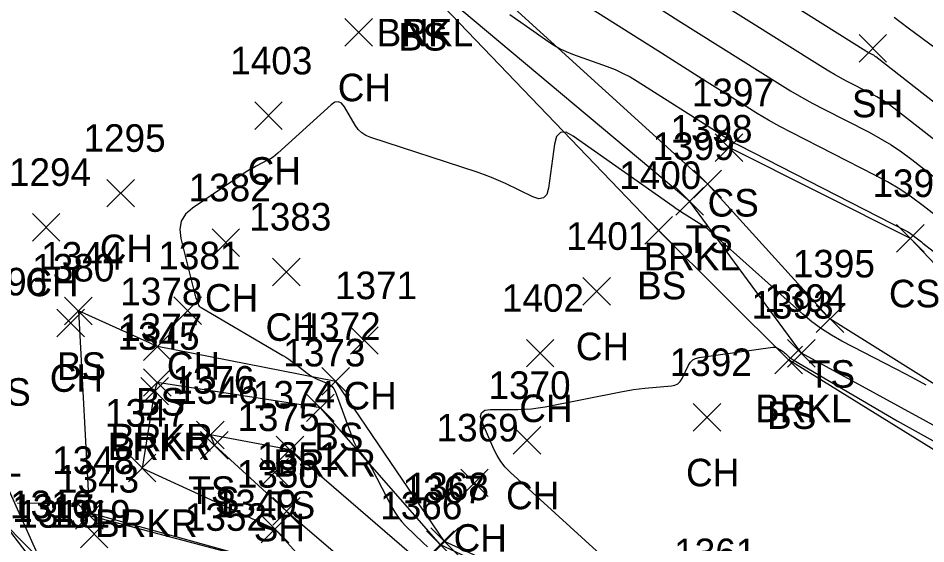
# Model space of a CAD drawing. Extents: x 1592612 to 1596497, y 111838 to 113741.
# Drawn here: x 1592923.4 to 1592989.2, y 113267.9 to 113306.1 of the extents above; entities that cross this region are included whole.
import ezdxf

# ---------------------------------------------------------------- set-up
doc = ezdxf.new("R2010")
doc.units = 0
for name, color, linetype in [('L_A', 7, 'Continuous'), ('L_I', 7, 'Continuous'), ('L_TIC', 7, 'Continuous'), ('LAWE', 7, 'Continuous'), ('LELB', 7, 'Continuous'), ('LSOGCMA', 7, 'Continuous'), ('LSOGCMI', 7, 'Continuous')]:
    doc.layers.add(name, color=color, linetype=linetype)

msp = doc.modelspace()

# ---------------------------------------------------------------- linework, layer by layer
at = {"layer": 'L_TIC'}
for points in [[(1592947.083, 113304.028), (1592949.083, 113306.028)], [(1592949.083, 113304.028), (1592947.083, 113306.028)], [(1592984.338, 113302.867), (1592986.338, 113304.867)], [(1592986.338, 113302.867), (1592984.338, 113304.867)], [(1592940.548, 113297.976), (1592942.548, 113299.976)], [(1592942.548, 113297.976), (1592940.548, 113299.976)], [(1592973.924, 113295.668), (1592975.924, 113297.668)], [(1592975.924, 113295.668), (1592973.924, 113297.668)], [(1592972.366, 113293.033), (1592974.366, 113295.033)], [(1592974.366, 113293.033), (1592972.366, 113295.033)], [(1592929.837, 113292.363), (1592931.837, 113294.363)], [(1592931.837, 113292.363), (1592929.837, 113294.363)], [(1592971.077, 113291.77), (1592973.077, 113293.77)], [(1592973.077, 113291.77), (1592971.077, 113293.77)], [(1592924.437, 113289.892), (1592926.437, 113291.892)], [(1592926.437, 113289.892), (1592924.437, 113291.892)], [(1592968.817, 113289.666), (1592970.817, 113291.666)], [(1592970.817, 113289.666), (1592968.817, 113291.666)], [(1592937.455, 113288.772), (1592939.455, 113290.772)], [(1592939.455, 113288.772), (1592937.455, 113290.772)], [(1592987.064, 113289.085), (1592989.064, 113291.085)], [(1592989.064, 113289.085), (1592987.064, 113291.085)], [(1592941.844, 113286.655), (1592943.844, 113288.655)], [(1592943.844, 113286.655), (1592941.844, 113288.655)], [(1592964.331, 113285.252), (1592966.331, 113287.252)], [(1592966.331, 113285.252), (1592964.331, 113287.252)], [(1592926.773, 113283.823), (1592928.773, 113285.823)], [(1592928.773, 113283.823), (1592926.773, 113285.823)], [(1592934.693, 113283.84), (1592936.693, 113285.84)], [(1592936.693, 113283.84), (1592934.693, 113285.84)], [(1592926.21, 113282.958), (1592928.21, 113284.958)], [(1592928.21, 113282.958), (1592926.21, 113284.958)], [(1592981.233, 113283.253), (1592983.233, 113285.253)], [(1592983.233, 113283.253), (1592981.233, 113285.253)], [(1592947.495, 113281.678), (1592949.495, 113283.678)], [(1592949.495, 113281.678), (1592947.495, 113283.678)], [(1592932.501, 113281.239), (1592934.501, 113283.239)], [(1592934.501, 113281.239), (1592932.501, 113283.239)], [(1592960.233, 113280.762), (1592962.233, 113282.762)], [(1592962.233, 113280.762), (1592960.233, 113282.762)], [(1592979.168, 113280.757), (1592981.168, 113282.757)], [(1592981.168, 113280.757), (1592979.168, 113282.757)], [(1592978.237, 113280.269), (1592980.237, 113282.269)], [(1592980.237, 113280.269), (1592978.237, 113282.269)], [(1592932.489, 113278.637), (1592934.489, 113280.637)], [(1592934.489, 113278.637), (1592932.489, 113280.637)], [(1592945.42, 113278.713), (1592947.42, 113280.713)], [(1592947.42, 113278.713), (1592945.42, 113280.713)], [(1592932.296, 113278.006), (1592934.296, 113280.006)], [(1592934.296, 113278.006), (1592932.296, 113280.006)], [(1592944.312, 113276.8), (1592946.312, 113278.8)], [(1592946.312, 113276.8), (1592944.312, 113278.8)], [(1592972.314, 113276.102), (1592974.314, 113278.102)], [(1592974.314, 113276.102), (1592972.314, 113278.102)], [(1592936.328, 113274.828), (1592938.328, 113276.828)], [(1592938.328, 113274.828), (1592936.328, 113276.828)], [(1592959.272, 113274.442), (1592961.272, 113276.442)], [(1592961.272, 113274.442), (1592959.272, 113276.442)], [(1592936.624, 113274.084), (1592938.624, 113276.084)], [(1592938.624, 113274.084), (1592936.624, 113276.084)], [(1592942.112, 113273.75), (1592944.112, 113275.75)], [(1592944.112, 113273.75), (1592942.112, 113275.75)], [(1592931.394, 113272.429), (1592933.394, 113274.429)], [(1592933.394, 113272.429), (1592931.394, 113274.429)], [(1592940.988, 113272.113), (1592942.988, 113274.113)], [(1592942.988, 113272.113), (1592940.988, 113274.113)], [(1592955.475, 113271.361), (1592957.475, 113273.361)], [(1592957.475, 113271.361), (1592955.475, 113273.361)], [(1592927.567, 113269), (1592929.567, 113271)], [(1592929.567, 113269), (1592927.567, 113271)], [(1592941.855, 113269.299), (1592943.855, 113271.299)], [(1592943.855, 113269.299), (1592941.855, 113271.299)], [(1592927.916, 113267.65), (1592929.916, 113269.65)], [(1592929.916, 113267.65), (1592927.916, 113269.65)], [(1592941.029, 113268.005), (1592943.029, 113270.005)], [(1592943.029, 113268.005), (1592941.029, 113270.005)], [(1592953.308, 113267.098), (1592955.308, 113269.098)], [(1592955.308, 113267.098), (1592953.308, 113269.098)], [(1592953.003, 113266.868), (1592955.003, 113268.868)], [(1592955.003, 113266.868), (1592953.003, 113268.868)]]:
    msp.add_lwpolyline(points, dxfattribs=at)
at = {"layer": 'LAWE'}
for points in [[(1593001.92, 113269.875), (1592980.168, 113281.757), (1592972.077, 113292.77), (1592952.739, 113309.006), (1592930.405, 113333.014), (1592916.015, 113354.051), (1592913.1, 113363.091), (1592910.596, 113379.281), (1592906.825, 113388.644), (1592902.208, 113400.349), (1592897.68, 113413.914), (1592895.157, 113422.89), (1592891.073, 113425.248), (1592889.456, 113425.542), (1592888.74, 113438.019), (1592887.745, 113444.76), (1592887.496, 113453.354)], [(1592916.07, 113291.076), (1592920.024, 113277.813), (1592925.099, 113266.526)], [(1592933.296, 113279.006), (1592932.394, 113273.429), (1592942.029, 113269.005), (1592952.201, 113257.701), (1592963.301, 113254.92), (1592970.038, 113260.36), (1592954.003, 113267.868), (1592945.312, 113277.8), (1592933.489, 113279.637)], [(1592933.489, 113279.637), (1592933.296, 113279.006)]]:
    msp.add_lwpolyline(points, dxfattribs=at)
at = {"layer": 'LELB'}
for points in [[(1593000.607, 113268.02), (1592979.237, 113281.269), (1592969.817, 113290.666), (1592952.505, 113308.706), (1592930.32, 113332.83), (1592915.558, 113354.032), (1592906.593, 113378.229), (1592901.651, 113400.349), (1592897.345, 113413.71), (1592894.471, 113422.658), (1592891.543, 113424.972)], [(1593002.844, 113271.334), (1592982.233, 113284.253), (1592973.366, 113294.033), (1592954.604, 113311.113), (1592933.333, 113334.792), (1592919.468, 113354.266), (1592918.171, 113363.34), (1592916.481, 113374.12), (1592914.915, 113386.717)], [(1593004.187, 113273.082), (1592988.064, 113290.085), (1592974.924, 113296.668)], [(1592927.773, 113284.823), (1592928.566, 113270), (1592940.359, 113266.861), (1592951.679, 113257.353), (1592963.255, 113254.887), (1592971.22, 113260.41), (1592954.308, 113268.098), (1592946.421, 113279.713), (1592933.501, 113282.239)], [(1592933.501, 113282.239), (1592927.774, 113284.823)], [(1592889.863, 113282.382), (1592901.59, 113280.696), (1592913.642, 113278.201), (1592924.996, 113266.796), (1592943.132, 113254.464), (1592958.132, 113248.138), (1592963.265, 113252.408), (1592986.408, 113242.634)], [(1592937.328, 113275.828), (1592937.624, 113275.085)], [(1592937.624, 113275.084), (1592942.855, 113270.299), (1592954.482, 113260.336), (1592963.803, 113255.326), (1592967.044, 113259.564), (1592952.439, 113266.709), (1592943.112, 113274.75), (1592937.328, 113275.828)]]:
    msp.add_lwpolyline(points, dxfattribs=at)
at = {"layer": 'LSOGCMA'}
msp.add_lwpolyline([(1592992.267, 113289.883), (1592988.984, 113292.45), (1592988.15, 113293.07), (1592987.289, 113293.649), (1592986.402, 113294.186), (1592985.487, 113294.681), (1592979.448, 113297.767), (1592978.61, 113298.208), (1592977.782, 113298.666), (1592976.965, 113299.143), (1592976.159, 113299.638), (1592972.953, 113301.657), (1592972.152, 113302.162), (1592971.351, 113302.668), (1592970.551, 113303.174), (1592969.751, 113303.682), (1592964.748, 113306.863)], dxfattribs=at)
at = {"layer": 'LSOGCMI'}
for points in [[(1592963.205, 113317.294), (1592984.839, 113303.675), (1592984.897, 113303.639), (1592984.956, 113303.605), (1592985.016, 113303.572), (1592985.076, 113303.54), (1592985.318, 113303.416), (1592985.378, 113303.384), (1592985.436, 113303.349), (1592985.492, 113303.311), (1592985.547, 113303.27), (1593008.745, 113285.131), (1593009.033, 113284.905), (1593009.32, 113284.679), (1593009.608, 113284.452), (1593009.894, 113284.224), (1593011.612, 113282.856)], [(1593010.438, 113281.005), (1593005.747, 113284.741), (1593004.965, 113285.363), (1593004.181, 113285.983), (1593003.396, 113286.601), (1593002.609, 113287.218), (1592986.852, 113299.539), (1592986.456, 113299.833), (1592986.049, 113300.107), (1592985.628, 113300.362), (1592985.195, 113300.596), (1592983.436, 113301.495), (1592982.999, 113301.725), (1592982.568, 113301.964), (1592982.142, 113302.212), (1592981.721, 113302.47), (1592967.256, 113311.577)], [(1592966.172, 113309.106), (1592966.855, 113308.673), (1592968.331, 113307.738), (1592969.808, 113306.804), (1592971.286, 113305.873), (1592978.603, 113301.266), (1592979.386, 113300.786), (1592980.18, 113300.323), (1592980.983, 113299.877), (1592981.796, 113299.45), (1592985.071, 113297.777), (1592985.878, 113297.34), (1592986.661, 113296.866), (1592987.421, 113296.355), (1592988.157, 113295.808), (1592996.474, 113289.304), (1592997.759, 113288.297), (1592999.042, 113287.287), (1593000.322, 113286.274), (1593001.601, 113285.258), (1593009.264, 113279.155)], [(1592959.041, 113306.326), (1592959.441, 113306.04), (1592959.842, 113305.756), (1592960.244, 113305.473), (1592961.853, 113304.345), (1592962.263, 113304.078), (1592962.688, 113303.839), (1592963.128, 113303.629), (1592963.583, 113303.448), (1592966.094, 113302.544), (1592966.659, 113302.323), (1592967.21, 113302.071), (1592967.745, 113301.79), (1592968.266, 113301.478), (1592974.123, 113297.754), (1592974.247, 113297.676), (1592974.371, 113297.597), (1592974.495, 113297.519), (1592974.619, 113297.441), (1592975.116, 113297.128), (1592975.241, 113297.051), (1592975.367, 113296.977), (1592975.495, 113296.906), (1592975.625, 113296.838), (1592987.753, 113290.641), (1592987.863, 113290.581), (1592987.971, 113290.516), (1592988.075, 113290.446), (1592988.175, 113290.371), (1592988.572, 113290.061), (1592988.671, 113289.983), (1592988.77, 113289.905), (1592988.869, 113289.827), (1592988.968, 113289.749), (1592989.717, 113289.152)], [(1593013.11, 113285.137), (1592991.918, 113302.277), (1592991.425, 113302.671), (1592990.928, 113303.06), (1592990.427, 113303.445), (1592989.922, 113303.824), (1592987.894, 113305.329), (1592987.39, 113305.709), (1592986.891, 113306.096)], [(1592989.211, 113279.453), (1592988.468, 113279.846), (1592987.724, 113280.238), (1592986.979, 113280.628), (1592986.234, 113281.017), (1592983.103, 113282.642), (1592982.348, 113283.065), (1592981.624, 113283.531), (1592980.93, 113284.043), (1592980.267, 113284.598), (1592974.098, 113290.097), (1592974.014, 113290.172), (1592973.931, 113290.247), (1592973.847, 113290.323), (1592973.765, 113290.399), (1592973.433, 113290.704), (1592973.349, 113290.778), (1592973.261, 113290.848), (1592973.171, 113290.914), (1592973.077, 113290.976), (1592971.813, 113291.768), (1592971.571, 113291.922), (1592971.332, 113292.079), (1592971.095, 113292.239), (1592970.86, 113292.402), (1592963.635, 113297.503), (1592963.108, 113297.777), (1592962.705, 113297.769), (1592962.424, 113297.479), (1592962.266, 113296.907), (1592961.836, 113293.719), (1592961.709, 113293.272), (1592961.477, 113293.02), (1592961.139, 113292.965), (1592960.696, 113293.105), (1592958.712, 113294.06), (1592958.213, 113294.29), (1592957.707, 113294.503), (1592957.194, 113294.699), (1592956.674, 113294.878), (1592948.953, 113297.392), (1592948.607, 113297.538), (1592948.305, 113297.737), (1592948.045, 113297.99), (1592947.828, 113298.295), (1592947.045, 113299.625), (1592946.838, 113299.883), (1592946.609, 113299.993), (1592946.357, 113299.956), (1592946.083, 113299.77), (1592942.236, 113296.273), (1592942.06, 113296.123), (1592941.876, 113295.986), (1592941.683, 113295.861), (1592941.482, 113295.748), (1592940.66, 113295.322), (1592940.456, 113295.213), (1592940.255, 113295.098), (1592940.058, 113294.977), (1592939.864, 113294.851), (1592936.042, 113292.286), (1592935.537, 113291.844), (1592935.227, 113291.328), (1592935.112, 113290.736), (1592935.192, 113290.07), (1592936.212, 113286.024), (1592936.236, 113285.936), (1592936.262, 113285.848), (1592936.29, 113285.762), (1592936.32, 113285.675), (1592936.445, 113285.332), (1592936.482, 113285.251), (1592936.531, 113285.18), (1592936.592, 113285.119), (1592936.665, 113285.068), (1592942.582, 113281.596), (1592942.805, 113281.461), (1592943.023, 113281.318), (1592943.236, 113281.169), (1592943.445, 113281.012), (1592944.351, 113280.31), (1592944.521, 113280.187), (1592944.698, 113280.076), (1592944.881, 113279.976), (1592945.071, 113279.887), (1592945.847, 113279.557), (1592946.025, 113279.46), (1592946.173, 113279.334), (1592946.291, 113279.179), (1592946.379, 113278.996), (1592947.65, 113275.521), (1592947.731, 113275.324), (1592947.826, 113275.136), (1592947.935, 113274.954), (1592948.058, 113274.781), (1592948.581, 113274.104), (1592948.707, 113273.933), (1592948.826, 113273.756), (1592948.937, 113273.574), (1592949.04, 113273.387), (1592950.492, 113270.602), (1592950.706, 113270.227), (1592950.948, 113269.873), (1592951.216, 113269.538), (1592951.511, 113269.223), (1592952.747, 113268.005), (1592953.065, 113267.711)], [(1592966.662, 113266.19), (1592959.065, 113273.132), (1592958.702, 113273.5), (1592958.383, 113273.9), (1592958.109, 113274.332), (1592957.88, 113274.796), (1592957.032, 113276.762), (1592956.922, 113277.161), (1592956.985, 113277.447), (1592957.222, 113277.618), (1592957.632, 113277.676), (1592959.619, 113277.679), (1592960.114, 113277.692), (1592960.607, 113277.729), (1592961.098, 113277.789), (1592961.586, 113277.874), (1592967.196, 113278.99), (1592967.601, 113279.065), (1592968.007, 113279.128), (1592968.415, 113279.18), (1592968.824, 113279.22), (1592970.749, 113279.383), (1592970.998, 113279.433), (1592971.209, 113279.538), (1592971.382, 113279.698), (1592971.517, 113279.914), (1592971.982, 113280.885), (1592972.117, 113281.103), (1592972.289, 113281.269), (1592972.499, 113281.383), (1592972.747, 113281.446), (1592978.102, 113282.203), (1592978.188, 113282.208), (1592978.27, 113282.198), (1592978.35, 113282.173), (1592978.426, 113282.134), (1592978.724, 113281.947), (1592978.797, 113281.898), (1592978.868, 113281.847), (1592978.937, 113281.792), (1592979.003, 113281.734), (1592979.276, 113281.483), (1592979.344, 113281.423), (1592979.415, 113281.368), (1592979.49, 113281.316), (1592979.567, 113281.268), (1592987.112, 113276.863), (1592988.401, 113276.124), (1592989.702, 113275.406)], [(1592940.241, 113266.943), (1592928.917, 113270.087), (1592928.829, 113270.122), (1592928.759, 113270.176), (1592928.706, 113270.247), (1592928.672, 113270.335), (1592928.529, 113270.875), (1592928.523, 113270.897), (1592928.517, 113270.919), (1592928.51, 113270.941), (1592928.503, 113270.963), (1592928.475, 113271.049), (1592928.466, 113271.068), (1592928.453, 113271.078), (1592928.437, 113271.082), (1592928.417, 113271.078), (1592927.874, 113270.883), (1592927.775, 113270.853), (1592927.675, 113270.831), (1592927.574, 113270.82), (1592927.47, 113270.817), (1592923.552, 113270.889), (1592923.361, 113270.871)], [(1592922.532, 113269.197), (1592924.283, 113266.909)]]:
    msp.add_lwpolyline(points, dxfattribs=at)

# ---------------------------------------------------------------- texts
at = {"layer": 'L_A'}
for s, p in [('BRKL', (1592949.385, 113304.006)), ('NF', (1592951.219, 113304.006)), ('BS', (1592950.945, 113303.706)), ('CH', (1592946.571, 113300.028)), ('SH', (1592983.826, 113298.867)), ('CH', (1592940.036, 113293.976)), ('CS', (1592973.365, 113291.668)), ('TS', (1592971.776, 113289.033)), ('CH', (1592929.325, 113288.363)), ('BRKL', (1592968.722, 113287.77)), ('CH', (1592923.925, 113285.892)), ('BS', (1592968.258, 113285.666)), ('CH', (1592936.943, 113284.772)), ('CS', (1592986.505, 113285.085)), ('CH', (1592941.333, 113282.655)), ('CH', (1592963.819, 113281.252)), ('BS', (1592926.214, 113279.823)), ('CH', (1592934.181, 113279.84)), ('CH', (1592925.699, 113278.958)), ('TS', (1592980.643, 113279.253)), ('BS', (1592920.754, 113277.948)), ('CH', (1592946.983, 113277.678)), ('BS', (1592931.942, 113277.239)), ('CH', (1592959.721, 113276.762)), ('BRKL', (1592976.813, 113276.757)), ('BS', (1592977.678, 113276.269)), ('BRKR', (1592930.079, 113274.637)), ('BS', (1592944.861, 113274.713)), ('BRKR', (1592929.886, 113274.006)), ('BRKL', (1592916.67, 113272.813)), ('BRKR', (1592941.902, 113272.8)), ('CH', (1592971.803, 113272.102)), ('TS', (1592935.738, 113270.828)), ('CH', (1592958.76, 113270.442)), ('TS', (1592936.033, 113270.084)), ('TS', (1592941.521, 113269.75)), ('BRKR', (1592928.985, 113268.429)), ('SH', (1592940.477, 113268.113)), ('CH', (1592954.963, 113267.361))]:
    msp.add_text(s, height=2, dxfattribs=at).set_placement(p)
at = {"layer": 'L_I'}
for s, p in [('1403', (1592938.776, 113301.976)), ('1397', (1592972.232, 113299.668)), ('1398', (1592970.673, 113297.033)), ('1295', (1592928.144, 113296.363)), ('1399', (1592969.376, 113295.77)), ('1294', (1592922.744, 113293.892)), ('1400', (1592966.959, 113293.666)), ('1382', (1592935.762, 113292.772)), ('1396', (1592985.316, 113293.085)), ('1383', (1592940.152, 113290.655)), ('1401', (1592963.126, 113289.252)), ('1344', (1592925.081, 113287.823)), ('1381', (1592933.567, 113287.84)), ('1380', (1592924.431, 113286.958)), ('1395', (1592979.54, 113287.253)), ('1296', (1592919.565, 113285.948)), ('1371', (1592946.369, 113285.678)), ('1378', (1592930.808, 113285.239)), ('1402', (1592958.461, 113284.762)), ('1394', (1592977.475, 113284.757)), ('1393', (1592976.544, 113284.269)), ('1372', (1592943.728, 113282.713)), ('1377', (1592930.796, 113282.637)), ('1345', (1592930.603, 113282.006)), ('1373', (1592942.619, 113280.8)), ('1392', (1592970.622, 113280.102)), ('1376', (1592934.58, 113278.828)), ('1346', (1592934.876, 113278.084)), ('1370', (1592957.492, 113278.442)), ('1374', (1592940.419, 113277.75)), ('1347', (1592929.701, 113276.429)), ('1375', (1592939.295, 113276.113)), ('1369', (1592953.727, 113275.361)), ('1348', (1592925.874, 113273)), ('1351', (1592940.729, 113273.299)), ('1343', (1592926.224, 113271.65)), ('1350', (1592939.25, 113272.005)), ('1367', (1592951.263, 113270.868)), ('1368', (1592951.568, 113271.098)), ('1316', (1592922.815, 113269.796)), ('1317', (1592922.973, 113269.526)), ('1349', (1592937.659, 113269.862)), ('1366', (1592949.644, 113269.709)), ('1318', (1592923.35, 113269.102)), ('1318', (1592923.35, 113269.102)), ('1319', (1592925.613, 113269.113)), ('1352', (1592935.49, 113268.879)), ('1361', (1592970.95, 113266.316))]:
    msp.add_text(s, height=2, dxfattribs=at).set_placement(p)

doc.saveas('drawing.dxf')
